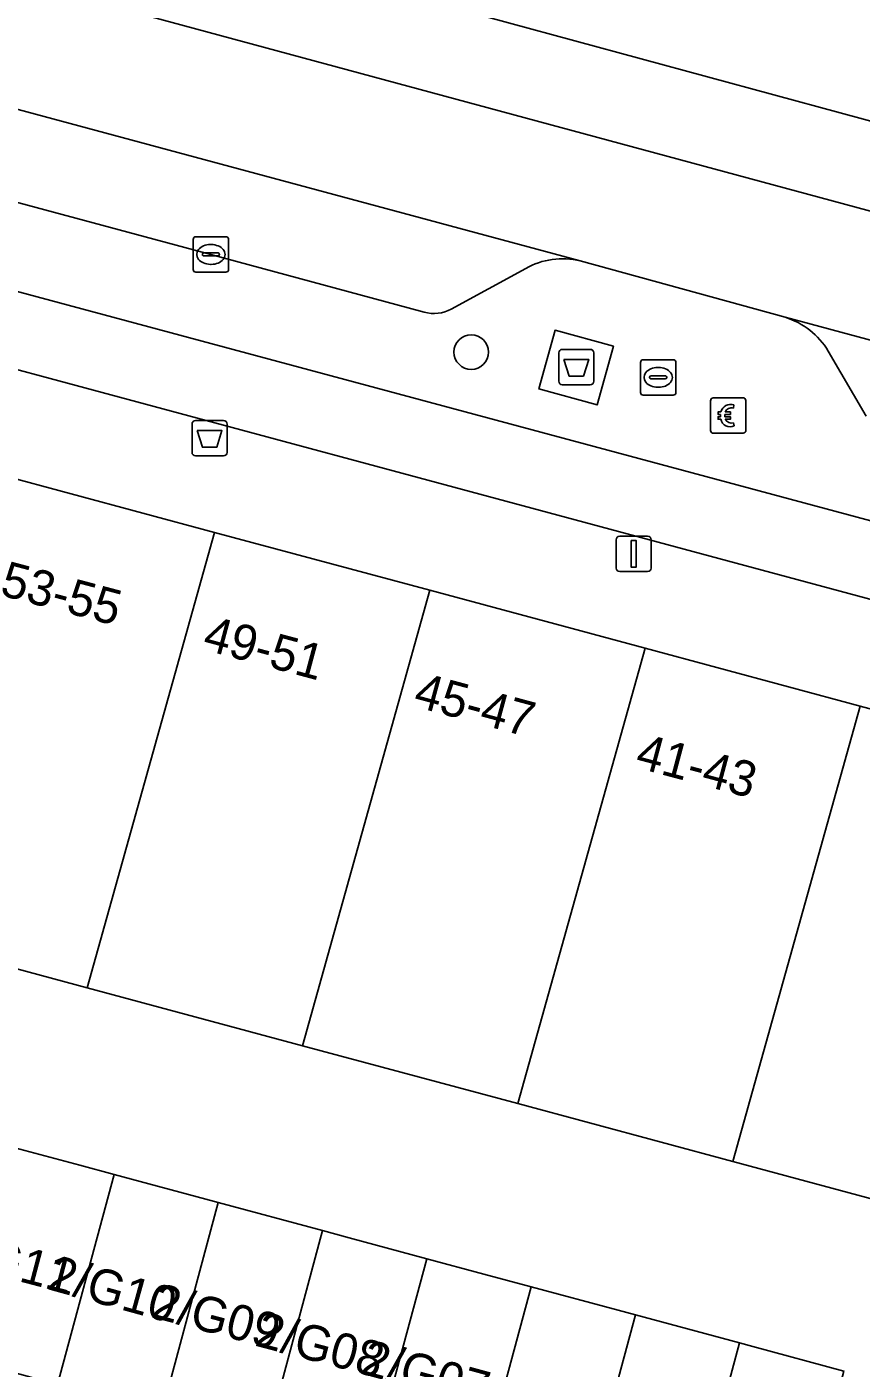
# Model space of a CAD drawing. Extents: x 160675 to 161153, y 383241 to 383714.
# Drawn here: x 160771.09 to 160794.67, y 383564.02 to 383601.94 of the extents above; entities that cross this region are included whole.
import ezdxf

# ---------------------------------------------------------------- set-up
doc = ezdxf.new("R2010")
doc.units = 0
for name, color, linetype in [('IMGEO_Afval_apart_plaats', 7, 'Continuous'), ('IMGEO_Afvalbak', 7, 'Continuous'), ('IMGEO_Berm_open', 7, 'Continuous'), ('IMGEO_Betaalautomaat', 7, 'Continuous'), ('IMGEO_Boom', 7, 'Continuous'), ('IMGEO_Erf', 7, 'Continuous'), ('IMGEO_Fietspad_gesloten', 7, 'Continuous'), ('IMGEO_Kolk', 7, 'Continuous'), ('IMGEO_Lichtmast', 7, 'Continuous'), ('IMGEO_OVBaan_gesloten', 7, 'Continuous'), ('IMGEO_Pand', 7, 'Continuous'), ('IMGEO_Pand_nummerreeks', 7, 'Continuous'), ('IMGEO_Parkeervlak_open', 7, 'Continuous'), ('IMGEO_Rijbaan_lokaal_gesloten', 7, 'Continuous'), ('IMGEO_Voetpad_gesloten', 7, 'Continuous'), ('IMGEO_Voetpad_open', 7, 'Continuous')]:
    doc.layers.add(name, color=color, linetype=linetype)

msp = doc.modelspace()

# ---------------------------------------------------------------- linework, layer by layer
at = {"layer": 'IMGEO_Afval_apart_plaats'}
for p, q in [((160786.227, 383592.823), (160787.017, 383592.823)), ((160787.017, 383592.823), (160786.227, 383592.823)), ((160786.127, 383591.923), (160786.127, 383592.723)), ((160786.127, 383592.723), (160786.127, 383591.923)), ((160787.117, 383592.723), (160787.117, 383591.923)), ((160787.117, 383591.923), (160787.117, 383592.723)), ((160787.017, 383591.823), (160786.227, 383591.823)), ((160786.227, 383591.823), (160787.017, 383591.823))]:
    msp.add_line(p, q, dxfattribs=at)
msp.add_lwpolyline([(160786.27, 383592.537), (160786.974, 383592.537), (160786.825, 383592.067), (160786.419, 383592.067), (160786.27, 383592.537)], dxfattribs=at)
for centre, start, end in [((160786.227, 383592.723), 90, 180), ((160786.227, 383592.723), 90, 180), ((160787.017, 383592.723), 0, 90), ((160787.017, 383592.723), 360, 90), ((160786.227, 383591.923), 180, 270), ((160786.227, 383591.923), 180, 270), ((160787.017, 383591.923), 270, 0), ((160787.017, 383591.923), 270, 0)]:
    msp.add_arc(centre, 0.1, start, end, dxfattribs=at)
at = {"layer": 'IMGEO_Afvalbak'}
for p, q in [((160775.762, 383589.912), (160775.762, 383590.712)), ((160775.762, 383590.712), (160775.762, 383589.912)), ((160775.862, 383590.812), (160776.652, 383590.812)), ((160776.652, 383590.812), (160775.862, 383590.812)), ((160776.752, 383590.712), (160776.752, 383589.912)), ((160776.752, 383589.912), (160776.752, 383590.712)), ((160776.652, 383589.812), (160775.862, 383589.812)), ((160775.862, 383589.812), (160776.652, 383589.812))]:
    msp.add_line(p, q, dxfattribs=at)
msp.add_lwpolyline([(160775.905, 383590.526), (160776.609, 383590.526), (160776.46, 383590.056), (160776.054, 383590.056), (160775.905, 383590.526)], dxfattribs=at)
for centre, start, end in [((160775.862, 383590.712), 90, 180), ((160775.862, 383590.712), 90, 180), ((160776.652, 383590.712), 0, 90), ((160776.652, 383590.712), 360, 90), ((160775.862, 383589.912), 180, 270), ((160775.862, 383589.912), 180, 270), ((160776.652, 383589.912), 270, 0), ((160776.652, 383589.912), 270, 0)]:
    msp.add_arc(centre, 0.1, start, end, dxfattribs=at)
at = {"layer": 'IMGEO_Berm_open'}
for points in [[(160753.356, 383599.164), (160754.374, 383598.874), (160872.54, 383567.128), (160873.601, 383566.834), (160874.194, 383569.11), (160871.092, 383569.968), (160860.355, 383572.895)], [(160782.323, 383593.874), (160776.292, 383595.507), (160765.431, 383598.425)], [(160785.193, 383595.109), (160783.089, 383593.961)], [(160792.524, 383593.731), (160786.733, 383595.326)], [(160794.817, 383590.934), (160793.746, 383592.772)]]:
    msp.add_lwpolyline(points, dxfattribs=at)
msp.add_lwpolyline([(160787.215, 383591.253), (160785.566, 383591.707), (160786.022, 383593.364), (160787.671, 383592.91)], close=True, dxfattribs=at)
for centre, radius, start, end in [((160786.238, 383593.268), 2.117, 76.4689, 119.5724), ((160782.597, 383594.879), 1.042, 254.7643, 298.1951), ((160791.875, 383591.646), 2.183, 31.0359, 72.716)]:
    msp.add_arc(centre, radius, start, end, dxfattribs=at)
at = {"layer": 'IMGEO_Betaalautomaat'}
for p, q in [((160790.417, 383590.528), (160790.417, 383591.369)), ((160790.417, 383591.369), (160790.417, 383590.528)), ((160790.492, 383591.452), (160791.333, 383591.452)), ((160791.333, 383591.452), (160790.492, 383591.452)), ((160791.416, 383591.378), (160791.416, 383590.537)), ((160791.416, 383590.537), (160791.416, 383591.378)), ((160790.7, 383590.916), (160790.7, 383590.984)), ((160790.821, 383590.984), (160790.821, 383590.916)), ((160791.079, 383591.257), (160791.062, 383591.157)), ((160791.066, 383590.751), (160791.088, 383590.664)), ((160791.342, 383590.453), (160790.501, 383590.453)), ((160790.501, 383590.453), (160791.342, 383590.453))]:
    msp.add_line(p, q, dxfattribs=at)
for points in [[(160790.7, 383590.984), (160790.631, 383590.984), (160790.631, 383591.053), (160790.71, 383591.053)], [(160790.705, 383590.847), (160790.631, 383590.847), (160790.631, 383590.916), (160790.7, 383590.916)], [(160790.832, 383591.053), (160790.979, 383591.053), (160790.979, 383590.984), (160790.821, 383590.984)], [(160790.821, 383590.916), (160790.979, 383590.916), (160790.979, 383590.847), (160790.835, 383590.847)]]:
    msp.add_lwpolyline(points, dxfattribs=at)
for centre, radius, start, end in [((160790.495, 383591.375), 0.0779, 92.4484, 184.2845), ((160790.495, 383591.375), 0.0779, 92.4484, 184.2845), ((160790.993, 383590.977), 0.293, 73.014, 165.0139), ((160791.339, 383591.375), 0.0779, 2.4484, 94.2845), ((160791.339, 383591.375), 0.0779, 2.4484, 94.2845), ((160790.999, 383590.99), 0.179, 69.3236, 159.5683), ((160790.495, 383590.531), 0.0779, 182.4484, 274.2845), ((160790.495, 383590.531), 0.0779, 182.4484, 274.2845), ((160790.966, 383590.902), 0.267, 191.8096, 297.0389), ((160790.999, 383590.917), 0.179, 202.7625, 291.8693), ((160791.339, 383590.531), 0.0779, 272.4484, 4.2845), ((160791.339, 383590.531), 0.0779, 272.4484, 4.2845)]:
    msp.add_arc(centre, radius, start, end, dxfattribs=at)
at = {"layer": 'IMGEO_Boom'}
msp.add_circle((160783.654, 383592.746), 0.489, dxfattribs=at)
at = {"layer": 'IMGEO_Erf'}
for points in [[(160815.386, 383563.308), (160809.303, 383564.947), (160803.219, 383566.585), (160797.136, 383568.224), (160791.052, 383569.862), (160784.969, 383571.501), (160778.885, 383573.14), (160772.802, 383574.778), (160766.719, 383576.417)], [(160770.612, 383570.292), (160772.593, 383569.758), (160773.558, 383569.498), (160776.397, 383568.734), (160776.505, 383568.704), (160779.452, 383567.911), (160780.202, 383567.709), (160782.399, 383567.117), (160784.006, 383566.684), (160785.346, 383566.323), (160787.811, 383565.659), (160788.293, 383565.529), (160791.24, 383564.736), (160791.615, 383564.635), (160794.187, 383563.942)]]:
    msp.add_lwpolyline(points, dxfattribs=at)
at = {"layer": 'IMGEO_Fietspad_gesloten'}
for points in [[(160741.54, 383600.127), (160851.652, 383570.489), (160869.912, 383565.633), (160904.417, 383556.04)], [(160904.814, 383558.169), (160877.012, 383565.887), (160875.567, 383566.288), (160873.601, 383566.834), (160872.54, 383567.128), (160754.374, 383598.874)]]:
    msp.add_lwpolyline(points, dxfattribs=at)
at = {"layer": 'IMGEO_Kolk'}
for p, q in [((160775.795, 383595.08), (160775.795, 383595.932)), ((160775.87, 383596.006), (160776.722, 383596.006)), ((160776.796, 383595.932), (160776.796, 383595.08)), ((160776.054, 383595.5), (160776.054, 383595.512)), ((160776.492, 383595.463), (160776.094, 383595.463)), ((160776.097, 383595.549), (160776.495, 383595.549)), ((160776.283, 383595.786), (160776.308, 383595.786)), ((160776.538, 383595.512), (160776.538, 383595.5)), ((160776.306, 383595.226), (160776.281, 383595.226)), ((160776.722, 383595.006), (160775.87, 383595.006)), ((160788.437, 383591.604), (160788.437, 383592.456)), ((160788.512, 383592.53), (160789.364, 383592.53)), ((160789.438, 383592.456), (160789.438, 383591.604)), ((160788.696, 383592.024), (160788.696, 383592.036)), ((160788.739, 383592.073), (160789.137, 383592.073)), ((160788.925, 383592.31), (160788.95, 383592.31)), ((160789.18, 383592.036), (160789.18, 383592.024)), ((160789.134, 383591.987), (160788.736, 383591.987)), ((160788.948, 383591.75), (160788.923, 383591.75)), ((160789.364, 383591.53), (160788.512, 383591.53))]:
    msp.add_line(p, q, dxfattribs=at)
for points in [[(160775.795, 383595.08), (160775.795, 383595.932)], [(160775.87, 383596.006), (160776.722, 383596.006)], [(160776.796, 383595.932), (160776.796, 383595.08)], [(160776.722, 383595.006), (160775.87, 383595.006)], [(160788.437, 383591.604), (160788.437, 383592.456)], [(160788.512, 383592.53), (160789.364, 383592.53)], [(160789.438, 383592.456), (160789.438, 383591.604)], [(160789.364, 383591.53), (160788.512, 383591.53)]]:
    msp.add_lwpolyline(points, dxfattribs=at)
for centre, radius, start, end in [((160775.872, 383595.93), 0.0765, 91.552, 178.448), ((160775.872, 383595.93), 0.0765, 91.552, 178.448), ((160776.72, 383595.93), 0.0765, 1.552, 88.448), ((160776.72, 383595.93), 0.0765, 1.552, 88.448), ((160776.094, 383595.509), 0.0403, 85.8775, 175.7526), ((160776.091, 383595.499), 0.0366, 178.938, 274.7102), ((160776.495, 383595.506), 0.043, 264.8664, 352.4533), ((160776.499, 383595.511), 0.0386, 1.7309, 96.639), ((160775.872, 383595.082), 0.0765, 181.552, 268.448), ((160775.872, 383595.082), 0.0765, 181.552, 268.448), ((160776.72, 383595.082), 0.0765, 271.552, 358.448), ((160776.72, 383595.082), 0.0765, 271.552, 358.448), ((160788.514, 383592.454), 0.0765, 91.552, 178.448), ((160788.514, 383592.454), 0.0765, 91.552, 178.448), ((160789.362, 383592.454), 0.0765, 1.552, 88.448), ((160789.362, 383592.454), 0.0765, 1.552, 88.448), ((160788.736, 383592.033), 0.0403, 85.8775, 175.7526), ((160788.733, 383592.023), 0.0366, 178.938, 274.7102), ((160789.137, 383592.03), 0.043, 264.8664, 352.4533), ((160789.141, 383592.035), 0.0386, 1.7309, 96.639), ((160788.514, 383591.606), 0.0765, 181.552, 268.448), ((160788.514, 383591.606), 0.0765, 181.552, 268.448), ((160789.362, 383591.606), 0.0765, 271.552, 358.448), ((160789.362, 383591.606), 0.0765, 271.552, 358.448)]:
    msp.add_arc(centre, radius, start, end, dxfattribs=at)
for centre, major_axis, ratio, start_param, end_param in [((160776.282, 383595.506), (-0.387, 0.002), 0.722429, 4.712389, 7.853982), ((160776.307, 383595.506), (-0.39, 0.002), 0.717154, 1.570796, 4.712389), ((160788.924, 383592.03), (-0.387, 0.002), 0.722429, 4.712389, 7.853982), ((160788.949, 383592.03), (-0.39, 0.002), 0.717154, 1.570796, 4.712389)]:
    msp.add_ellipse(centre, major_axis=major_axis, ratio=ratio, start_param=start_param, end_param=end_param, dxfattribs=at)
at = {"layer": 'IMGEO_Lichtmast'}
for p, q in [((160787.85, 383587.542), (160788.64, 383587.542)), ((160788.64, 383587.542), (160787.85, 383587.542)), ((160787.75, 383586.642), (160787.75, 383587.442)), ((160787.75, 383587.442), (160787.75, 383586.642)), ((160788.74, 383587.442), (160788.74, 383586.642)), ((160788.74, 383586.642), (160788.74, 383587.442)), ((160788.64, 383586.542), (160787.85, 383586.542)), ((160787.85, 383586.542), (160788.64, 383586.542))]:
    msp.add_line(p, q, dxfattribs=at)
msp.add_lwpolyline([(160788.17, 383587.417), (160788.32, 383587.417), (160788.32, 383586.667), (160788.17, 383586.667), (160788.17, 383587.417)], dxfattribs=at)
for centre, start, end in [((160787.85, 383587.442), 90, 180), ((160787.85, 383587.442), 90, 180), ((160788.64, 383587.442), 0, 90), ((160788.64, 383587.442), 360, 90), ((160787.85, 383586.642), 180, 270), ((160787.85, 383586.642), 180, 270), ((160788.64, 383586.642), 270, 0), ((160788.64, 383586.642), 270, 0)]:
    msp.add_arc(centre, 0.1, start, end, dxfattribs=at)
at = {"layer": 'IMGEO_OVBaan_gesloten'}
msp.add_lwpolyline([(160765.95, 383607.15), (160797.835, 383598.49), (160870.684, 383578.867), (160946.568, 383557.927)], dxfattribs=at)
at = {"layer": 'IMGEO_Pand'}
for points in [[(160776.398, 383587.651), (160770.314, 383589.29), (160766.719, 383576.417), (160772.802, 383574.778)], [(160776.398, 383587.651), (160772.802, 383574.778), (160778.885, 383573.14), (160782.481, 383586.013)], [(160778.885, 383573.14), (160784.969, 383571.501), (160788.565, 383584.374), (160782.481, 383586.013)], [(160784.969, 383571.501), (160791.052, 383569.862), (160794.648, 383582.735), (160788.565, 383584.374)], [(160800.731, 383581.097), (160794.648, 383582.735), (160791.052, 383569.862), (160797.136, 383568.224)], [(160773.558, 383569.498), (160772.593, 383569.758), (160770.612, 383570.292), (160769.014, 383564.36), (160770.995, 383563.826), (160771.961, 383563.566)], [(160773.558, 383569.498), (160771.961, 383563.566), (160774.799, 383562.801), (160774.907, 383562.772), (160776.505, 383568.704), (160776.397, 383568.734)], [(160779.452, 383567.911), (160776.505, 383568.704), (160774.907, 383562.772), (160777.854, 383561.978)], [(160779.452, 383567.911), (160777.854, 383561.978), (160778.604, 383561.776), (160780.801, 383561.184), (160782.399, 383567.117), (160780.202, 383567.709)], [(160783.748, 383560.389), (160785.346, 383566.323), (160784.006, 383566.684), (160782.399, 383567.117), (160780.801, 383561.184), (160782.408, 383560.751)], [(160788.293, 383565.529), (160787.811, 383565.659), (160785.346, 383566.323), (160783.748, 383560.389), (160786.212, 383559.725), (160786.695, 383559.595)], [(160788.293, 383565.529), (160786.695, 383559.595), (160789.642, 383558.801), (160791.24, 383564.736)], [(160791.24, 383564.736), (160789.642, 383558.801), (160790.016, 383558.7), (160792.589, 383558.007), (160794.187, 383563.942), (160791.615, 383564.635)]]:
    msp.add_lwpolyline(points, close=True, dxfattribs=at)
at = {"layer": 'IMGEO_Parkeervlak_open'}
for points in [[(160786.733, 383595.326), (160762.407, 383601.874)], [(160765.431, 383598.425), (160776.292, 383595.507), (160782.323, 383593.874)], [(160783.089, 383593.961), (160785.193, 383595.109)], [(160819.386, 383586.497), (160792.524, 383593.731)], [(160793.746, 383592.772), (160794.817, 383590.934)]]:
    msp.add_lwpolyline(points, dxfattribs=at)
for centre, radius, start, end in [((160786.238, 383593.268), 2.117, 76.4689, 119.5724), ((160782.597, 383594.879), 1.042, 254.7643, 298.1951), ((160791.875, 383591.646), 2.183, 31.0359, 72.716)]:
    msp.add_arc(centre, radius, start, end, dxfattribs=at)
at = {"layer": 'IMGEO_Rijbaan_lokaal_gesloten'}
for points in [[(160748.774, 383605.431), (160752.694, 383604.486), (160754.68, 383603.938), (160760.442, 383602.399), (160762.407, 383601.874), (160786.733, 383595.326), (160792.524, 383593.731), (160819.386, 383586.497), (160826.28, 383584.667), (160844.949, 383579.673), (160848.337, 383578.365), (160853.656, 383575.522)], [(160869.874, 383576.512), (160797.171, 383596.125), (160768.531, 383603.87)]]:
    msp.add_lwpolyline(points, dxfattribs=at)
at = {"layer": 'IMGEO_Voetpad_gesloten'}
msp.add_lwpolyline([(160787.671, 383592.91), (160786.022, 383593.364), (160785.566, 383591.707), (160787.215, 383591.253)], close=True, dxfattribs=at)
at = {"layer": 'IMGEO_Voetpad_open'}
for points in [[(160768.531, 383603.87), (160797.171, 383596.125), (160797.835, 383598.49), (160765.95, 383607.15)], [(160740.618, 383600.266), (160739.966, 383597.73), (160740.363, 383597.607), (160740.309, 383597.372), (160745.98, 383595.844), (160752.064, 383594.206), (160758.147, 383592.567), (160764.231, 383590.928), (160770.314, 383589.29), (160776.398, 383587.651), (160782.481, 383586.013), (160788.565, 383584.374), (160794.648, 383582.735), (160800.731, 383581.097), (160806.815, 383579.458), (160812.898, 383577.819), (160818.982, 383576.181), (160825.065, 383574.542)], [(160851.652, 383570.489), (160741.54, 383600.127)]]:
    msp.add_lwpolyline(points, dxfattribs=at)

# ---------------------------------------------------------------- texts
at = {"layer": 'IMGEO_Pand_nummerreeks'}
for s, rotation, p in [('53-55', 345.1206, (160770.299, 383585.884)), ('49-51', 345.0004, (160776.025, 383584.347)), ('45-47', 344.8828, (160781.984, 383582.742)), ('41-43', 345.0686, (160788.254, 383581.013)), ('2/G11', 345.272, (160768.755, 383567.035)), ('2/G10', 344.5038, (160771.639, 383566.266)), ('2/G09', 345.1684, (160774.574, 383565.474)), ('2/G08', 345.2204, (160777.504, 383564.669)), ('2/G07', 344.7753, (160780.49, 383563.879))]:
    msp.add_text(s, height=1, rotation=rotation, dxfattribs=at).set_placement(p)

doc.saveas('drawing.dxf')
